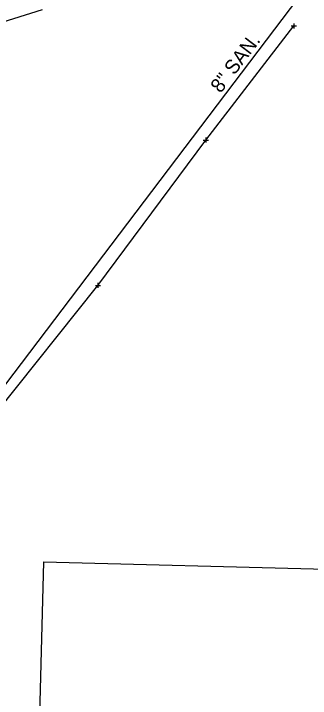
# Model space of a CAD drawing. Extents: x 1391912 to 1392597, y 304167 to 305226.
# Drawn here: x 1392438.8 to 1392497.1, y 304311.7 to 304446.3 of the extents above; entities that cross this region are included whole.
import ezdxf

# ---------------------------------------------------------------- set-up
doc = ezdxf.new("R2010")
doc.units = 0
for name, color, linetype in [('BD_X_Building', 7, 'Continuous'), ('RW_X_Esmt_SH', 7, 'Continuous'), ('SV_X_Break_Lines', 7, 'Continuous'), ('SV_X_Terrain_Boundary', 7, 'Continuous'), ('SV_X_Text', 7, 'Continuous'), ('UT_X_Gas', 7, 'Continuous'), ('UT_X_Sanitary_Line', 7, 'Continuous')]:
    doc.layers.add(name, color=color, linetype=linetype)

msp = doc.modelspace()

# ---------------------------------------------------------------- linework, layer by layer
at = {"layer": 'BD_X_Building'}
for q in [(1392442.59, 304257.82), (1392545.29, 304335.95)]:
    msp.add_line((1392444.67, 304338.54), q, dxfattribs=at)
at = {"layer": 'RW_X_Esmt_SH'}
for p, q in [((1392493.38, 304443.91), (1392494.38, 304443.91)), ((1392493.88, 304444.41), (1392493.88, 304443.41)), ((1392493.88, 304443.91), (1392493.88, 304443.91)), ((1392476.09, 304421.48), (1392477.09, 304421.48)), ((1392476.59, 304421.98), (1392476.59, 304420.98)), ((1392476.59, 304421.48), (1392476.59, 304421.48)), ((1392454.87, 304392.91), (1392455.87, 304392.91)), ((1392455.37, 304393.41), (1392455.37, 304392.41)), ((1392455.37, 304392.91), (1392455.37, 304392.91))]:
    msp.add_line(p, q, dxfattribs=at)
at = {"layer": 'SV_X_Break_Lines'}
msp.add_open_spline([(1392439.02, 304468.35), (1392430.22, 304466.36), (1392417.03, 304460.14), (1392402.39, 304445.83), (1392398.08, 304431.17), (1392394.86, 304407.24), (1392393.94, 304370.59), (1392388.07, 304338.52), (1392384.62, 304321.92)], degree=3, dxfattribs=at)
at = {"layer": 'SV_X_Terrain_Boundary'}
msp.add_lwpolyline([(1392444.41, 304447.07), (1392426.36, 304441.44), (1392414.71, 304421.65), (1392409.91, 304371.29), (1392404.17, 304319.57), (1392396.72, 304320.72), (1392384.62, 304321.92), (1392382.8, 304322.14), (1392368.06, 304323.26), (1392363.84, 304323.44), (1392359.73, 304323.64), (1392349.04, 304335.4), (1392336.91, 304335.98), (1392325.19, 304324.71), (1392313.17, 304324.96)], dxfattribs=at)
at = {"layer": 'UT_X_Gas'}
msp.add_lwpolyline([(1392399.55, 304321.52), (1392415.67, 304342.75), (1392435.46, 304368.01), (1392455.37, 304392.91), (1392476.59, 304421.48), (1392493.88, 304443.91)], dxfattribs=at)
at = {"layer": 'UT_X_Sanitary_Line'}
msp.add_line((1392394.73, 304317.39), (1392509.85, 304469.25), dxfattribs=at)

# ---------------------------------------------------------------- texts
at = {"layer": 'SV_X_Text'}
msp.add_text('8" SAN.', height=2.8, rotation=52.8361, dxfattribs=at).set_placement((1392479.5, 304430.54))

doc.saveas('drawing.dxf')
